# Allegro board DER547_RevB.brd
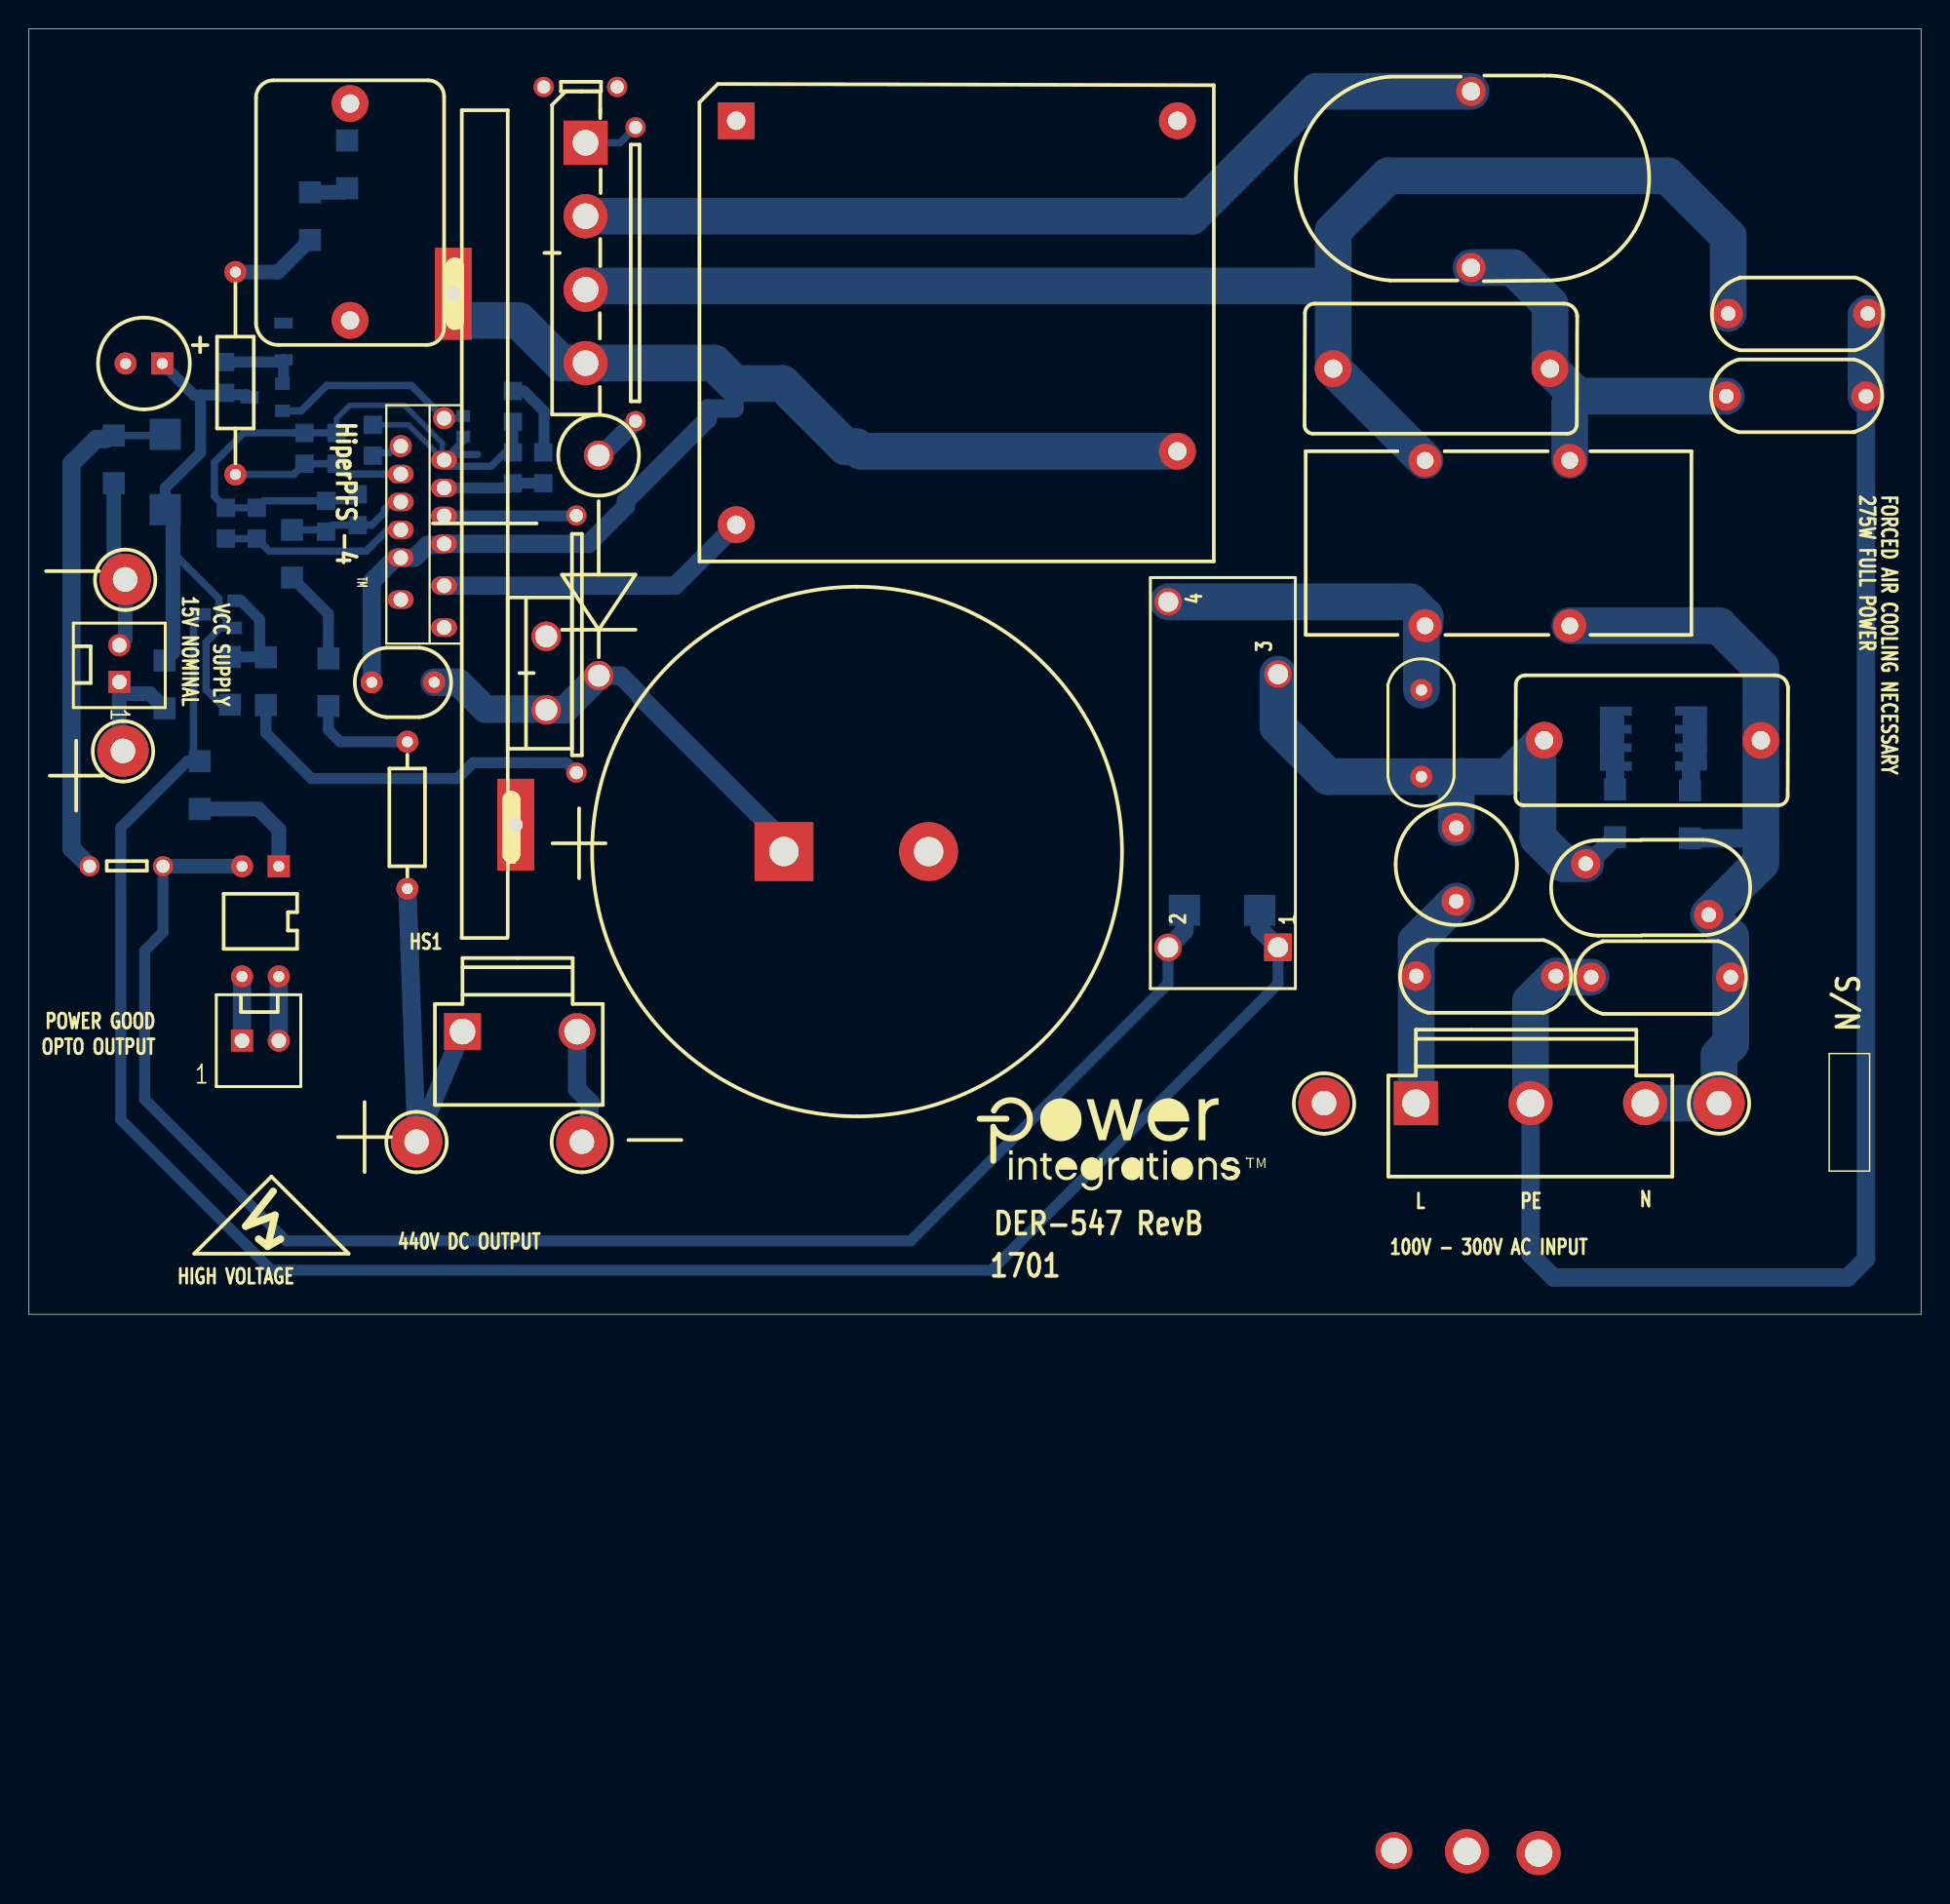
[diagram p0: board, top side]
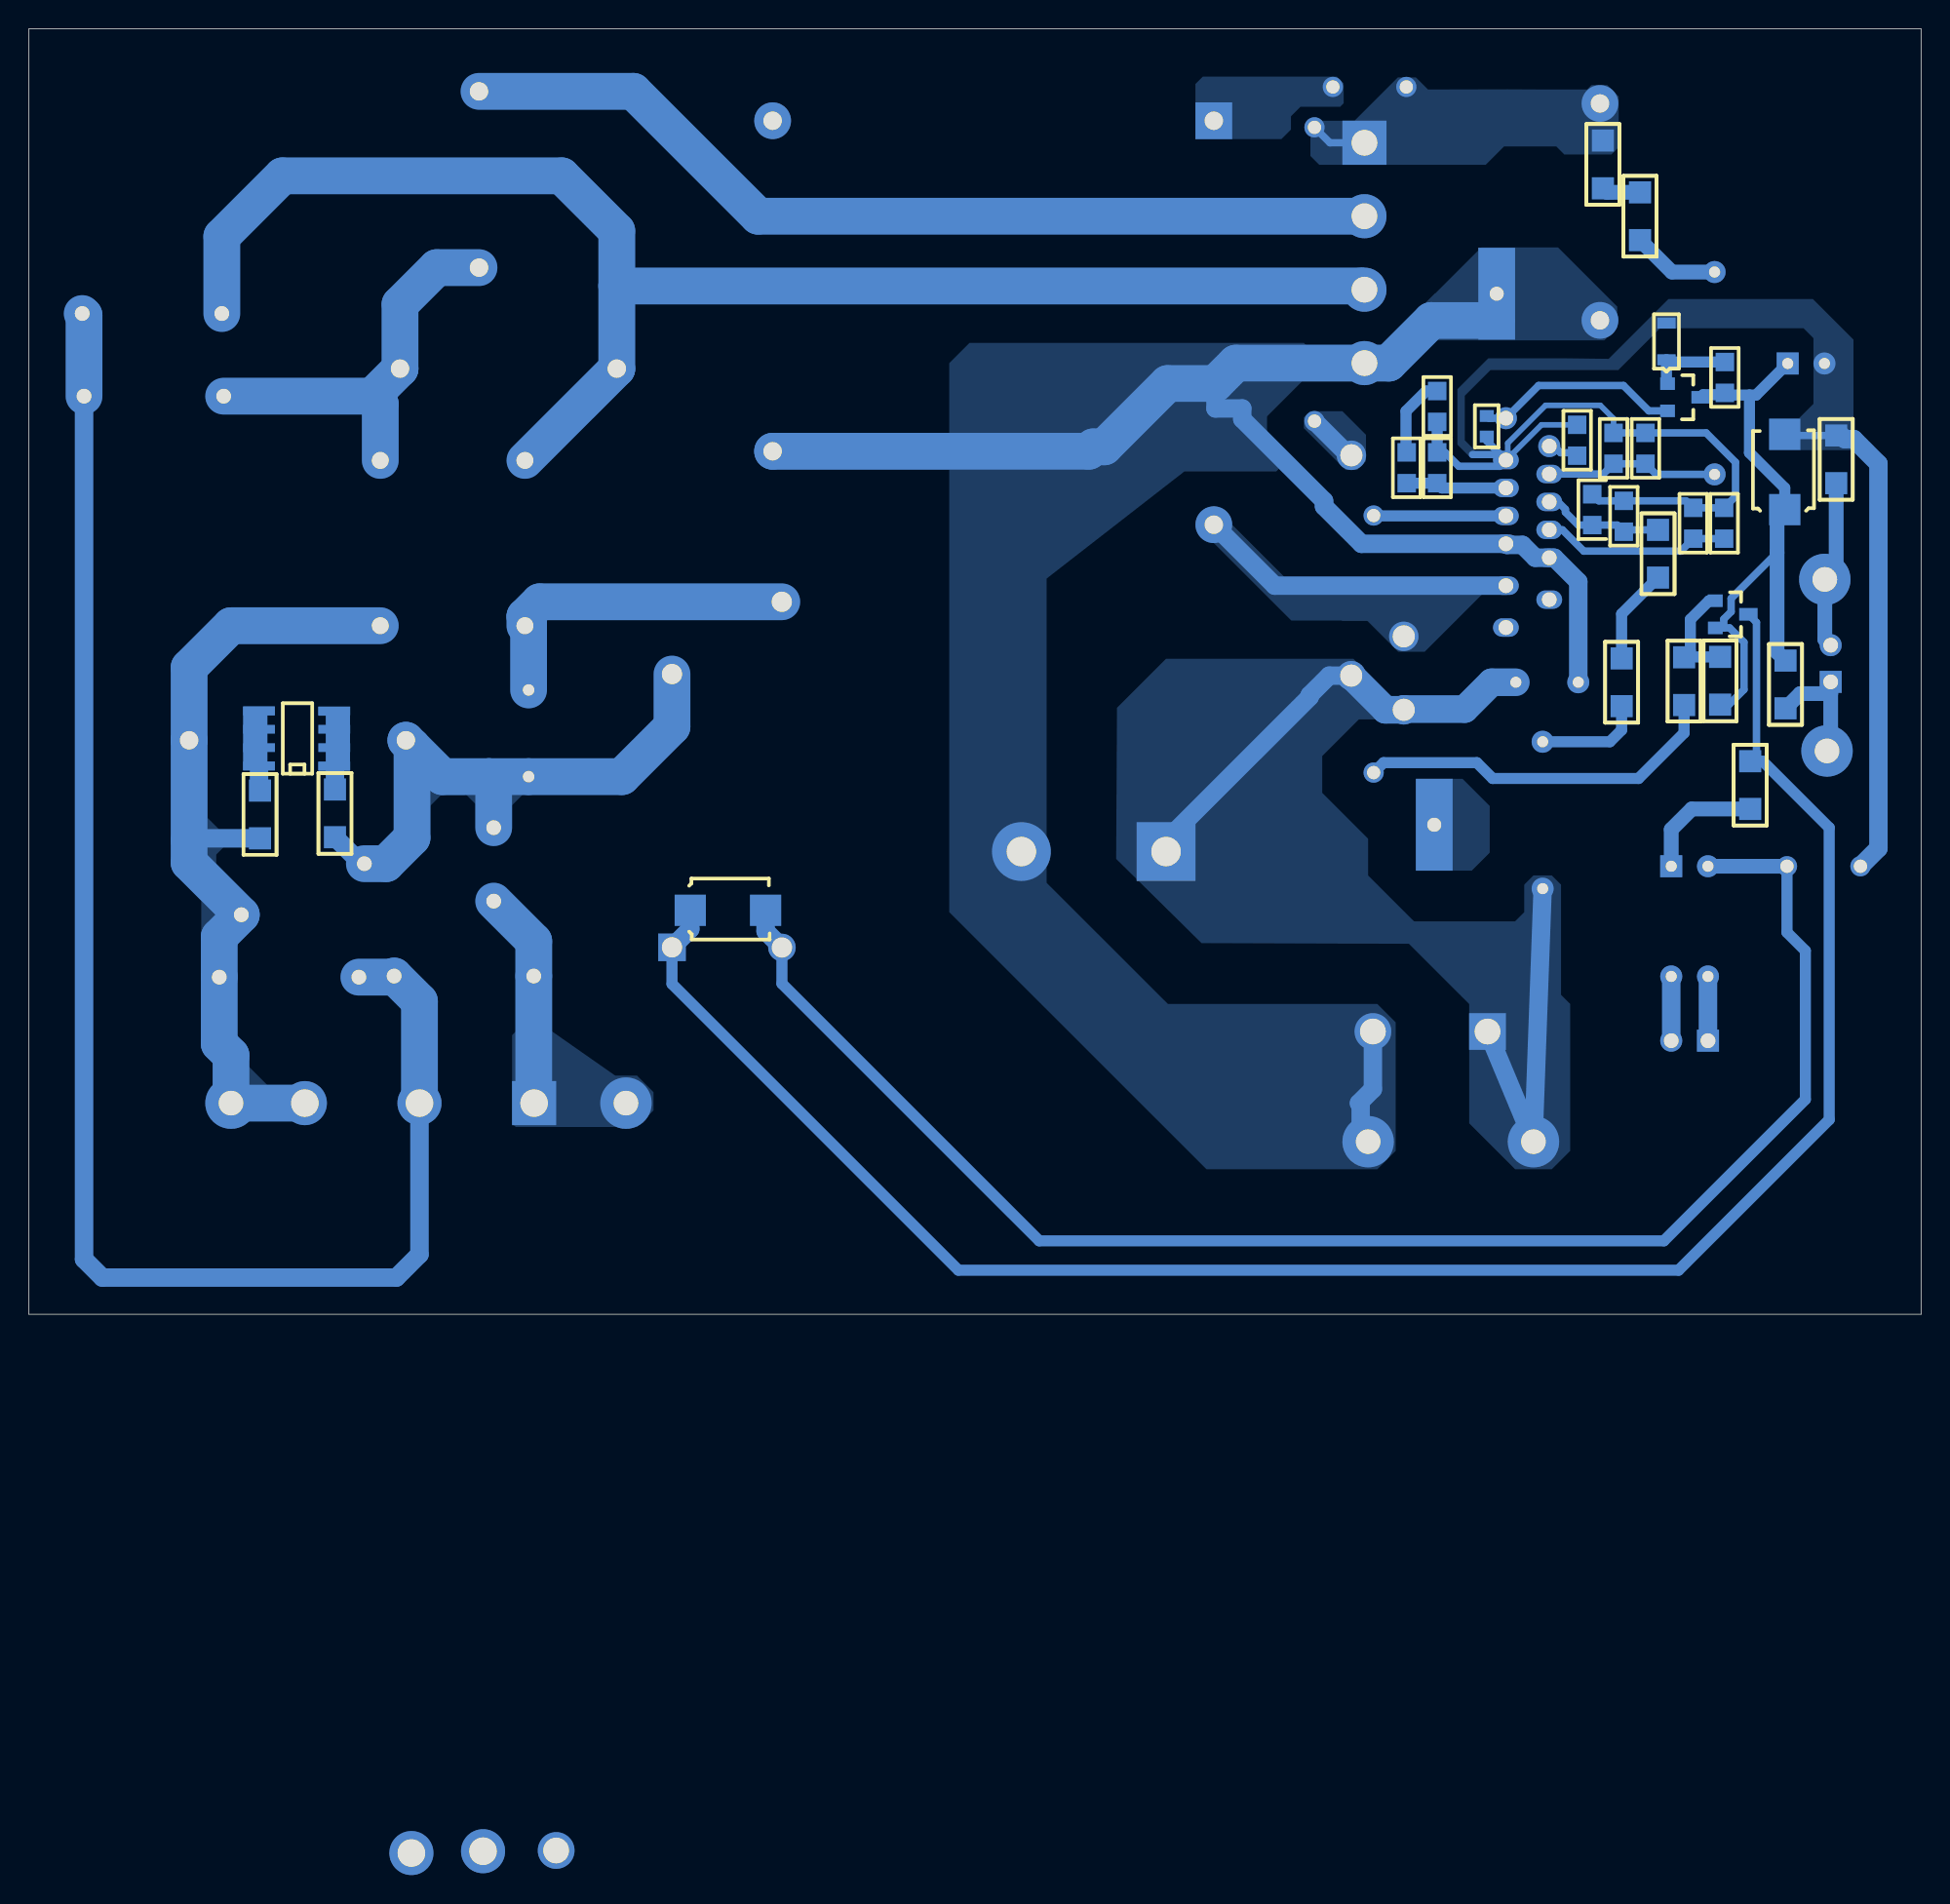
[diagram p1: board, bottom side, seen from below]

Outline 130.81 x 88.9 mm; copper layers: TOP, BOTTOM. Coordinates in mm from the lower left corner of the outline.
Outline path: 0,88.9 130.81,88.9 130.81,0 0,0 0,88.9

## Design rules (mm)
constraint set DEFAULT: min track width 0.508

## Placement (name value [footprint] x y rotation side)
BR1  GBU8K-BP  [PIDAXBRIDGEGBU8]  38.48 81.03 270 top
C1  680 pF  [PINPYCAPRAD470X210LS380040]  95.91 23.39 0 top
C2  680 pF  [PINPYCAPRAD470X210LS380040]  108 23.32 0 top
C3  0.33 uF  [PI_NP_CAPRAD709X354LS590D050]  104.75 39.7 0 top
C4  0.33 uF  [PI_NP_CAPRAD709X354LS590D050]  90.17 65.41 0 top
C5  680 pF  [PINPYCAPRAD470X210LS380040]  117.47 69.22 0 top
C6  680 pF  [PINPYCAPRAD470X210LS380040]  127 63.5 180 top
C7  0.33 uF  [PI_NP_CAPRAD717X472LS590D050]  22.2 83.74 270 top
C8  47 uF  [PIPOLCAPCYLD250LS100030]  9.22 65.76 180 top
C9  1 uF  [PISMC0603]  30.02 62.13 270 bottom
C10  1 uF  [PISMC0805]  23.77 59.39 90 bottom
C11  470 pF  [PISMC0805]  21.26 58.83 90 bottom
C12  100 nF  [PISMC0805]  33.45 57.48 90 bottom
C13  1 uF  [PISMC0805]  33.45 63.86 270 bottom
C14  1 nF  [PISMC0805]  15.75 53.64 90 bottom
C15  10 nF  [PI_NP_CAP250X200LS170D030]  28.02 43.71 180 top
C16  470 pF  [PISMC0805]  22.73 54.58 90 bottom
C18  180 uF  [PIPOLCAPCLYD1377LS394060]  52.2 32 0 top
D1  S1AB-13-F  [PISMSMB]  85.09 27.94 180 bottom
D2  1N5407-E3/54  [PIDV600X200X060DO14]  39.4 44.17 90 top
D3  S1AB-13-F  [PISMSMB]  9.42 55.65 90 bottom
D4  LXA06T600  [PIDVT0220ACREVA]  35.76 46.89 270 top
F1  5 A  [PI_TR5_SUBMIN_FUSE]  98.68 28.57 90 top
HS1  HEATSINK,  FAB, WITH BRKT, DER547, PI CUST  [PI_HS_DER394_EESIP]  33.1 26.11 90 top
J1  CON5  [PI_HDR_5PIN]  95.89 14.61 270 top
J2  CON2  [PI_MOLEX_2POL]  14.73 18.92 0 top
J3  CON3  [PI_HDR_3PIN_LOCK]  29.97 19.56 270 top
J4  CON2  [PI_MOLEX_2POL]  6.25 43.74 90 top
JP1  J  [PI_JUMPER200]  35.59 84.89 0 top
JP3  J  [PI_JUMPER200]  4.19 30.99 0 top
JP4  J  [PI_JUMPER800]  41.94 82.09 270 top
JP5  J  [PI_JUMPER700]  37.85 37.47 90 top
L1  400 uH  [PI_BOBBIN_BPQ32_20_32-00298-00]  48.9 82.55 0 top
L2  9 mH  [PI_IND_4P_500X1050LS450D46_R1]  96.52 47.62 90 top
L3  330 uH  [PI_TOROID_2P_550X950_LS480_D050]  99.69 72.39 90 top
NOREF  -  []  -213.36 -114.68 0 top
NOREF#2  -  []  0 0 90 top
NOREF#3  -  []  -135.54 84.33 0 top
NOREF#4  -  []  0 88.9 0 top
NOREF#5  -  []  65.53 14.99 0 top
Q1  -  [PISMSOT23132]  14.22 47.47 270 bottom
Q2  MMBT4401LT1G  [PISMSOT23132]  17.53 62.48 270 bottom
R1  510 k  [PISMR1206]  109.65 32.99 90 bottom
R2  510 k  [PISMR1206]  114.83 36.22 270 bottom
R3  10.0 k  [PISMR1206]  13.89 42.16 90 bottom
R4  16.2 k  [PISMR1206]  16.38 45.44 270 bottom
R5  3.01 k  [PISMR1206]  11.81 38.25 270 bottom
R6  1  [PISMR1206]  9.37 41.91 90 bottom
R7  1  [PISMR1206]  5.87 57.48 90 bottom
R8  2.21 k  [PISMR0805]  13.56 63.73 90 bottom
R10  6.2 M  [PISMR1206]  22 81.18 270 bottom
R11  6.2 M  [PISMR1206]  19.43 77.6 270 bottom
R12  3.74 M  [PI14WVRESD100LS100D030]  14.27 70.79 270 top
R13  143 k  [PISMR0805]  19.05 58.83 90 bottom
R14  30.1 k  [PISMR0805]  35.56 57.48 90 bottom
R15  332 k  [PISMR0805]  13.61 53.64 90 bottom
R16  3.74 M  [PI14WVRESD100LS100D030#2]  26.16 29.44 90 top
R17  6.2 M  [PISMR1206]  20.7 42.06 90 bottom
R18  6.2 M  [PISMR1206]  18.19 54.25 270 bottom
R19  143 k  [PISMR0805]  20.55 56.26 270 bottom
RL1  SPST NO  [PI_RLY-OMRON-G6RL-1A]  86.36 25.4 90 top
RT1  2.5  [PI_RAD180X395LS235D031]  96.27 37.19 90 top
RV1  420 Vac  [PIDISC500X225LS335X140040]  107.62 31.17 0 top
TP1  CON1  [PITPKEYSTONE125X125]  89.53 14.61 0 top
TP2  CON1  [PITPKEYSTONE125X125]  116.84 14.61 0 top
TP4  CON1  [PITPKEYSTONE125X125]  6.5 38.96 0 top
TP5  CON1  [PITPKEYSTONE125X125]  6.65 50.83 0 top
TP6  CON1  [PITPKEYSTONE125X125]  26.8 11.94 0 top
TP7  CON1  [PITPKEYSTONE125X125]  38.23 11.94 0 top
U1  PFS7627H  [PI_IC_ESIP16-13_SOCKET_HPII]  28.7 61.98 270 top
U2  CAP200DG  [PI_IC_SMD_SO8_CAPZERO]  109.7 37.92 90 bottom
U3  LTV817A  [PI_DIP4]  17.27 30.99 180 top
VR1  BZX384-B13,115  [PISMSOD323]  17.6 66.01 90 bottom

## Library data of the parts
BR1 = DISCRETE BRIDGE_+~~-
C1 C2 C5 C6 = CAP NP: tolerance: 20
C3 C4 C7 C9-C16 = CAP NP
C8 = CAP POL: alternate symbols: (pipolcapcyld250ls100030h); tolerance: 20
C18 = CAP POL
D1 D3 D4 = DIODE
D2 = DIODE: alternate symbols: (pidax800x225060do15do201ad,pidv300x200x060do14wbead,pidv600x200x060do14)
F1 = FUSE
HS1 = HS-PI_CUSTOM2
J1 = CON5
J2 J4 = CON2
J3 = CON3
JP1 JP3-JP5 = JUMPER_1
L1 = INDUCTOR_DER394_32-00298-00
L2 = INDUCTOR_4P_revB
L3 = INDUCTOR
Q1 = PNP_BEC_PISMSOT23132_MMBT4403
Q2 = NPN_BEC
R1-R8 R10 R11 R13-R15 R17-R19 = R
R12 R16 = R: alternate symbols: (pi14wvresd100ls200d030,pi14wresd100ls400d030,pi14wresd100ls500d030)
RL1 = RELAY SPST_NO_OMRON-G6RL
RT1 = THERMISTOR
RV1 = VARISTOR
TP1 TP2 TP4-TP7 = TESTPOINT
U1 = HIPERPFS-4-eSIP-16G: alternate symbols: (pi_ic_esip16-13_socket_hpii,pi_ic_esip16-13_oval_hpii,pi_ic_eesip_socket)
U2 = CAPZero
U3 = OPTO_DIP
VR1 = DIODE_ZENER

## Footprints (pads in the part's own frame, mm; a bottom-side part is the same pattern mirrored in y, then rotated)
PI14WVRESD100LS100D030
  round 1.524 hole 0.762: 1(-1.295,0) 2(12.7,0)
PI14WVRESD100LS100D030#2
  round 1.524 hole 0.762: 1(0,0) 2(10.16,0)
PI_BOBBIN_BPQ32_20_32-00298-00
  round 2.54 hole 1.27: (30.5,0) 6(0,-27.94) 8(30.5,-22.86)
  rect 2.54x2.54 hole 1.27: 1(0,0)
PI_DIP4
  rect 1.524x1.524 hole 0.762: 1(0,0)
  round 1.524 hole 0.762: 2(2.54,0) 3(2.54,7.62) 4(0,7.62)
PI_HDR_3PIN_LOCK
  rect 2.54x2.54 hole 1.778: 1(0,0)
  round 2.54 hole 1.778: 2(56.642,64.389) 3(0,7.925)
PI_HDR_5PIN
  rect 3.048x3.048 hole 1.905: 1(0,0)
  round 3.048 hole 1.905: 2(51.74,3.531) 3(0,7.925) 4(51.867,8.484) 5(0,15.85)
PI_HS_DER394_EESIP
  rect 6.35x2.54 hole 0.965: 1(7.747,-0.559) 2(44.475,3.759)
PI_IC_ESIP16-13_SOCKET_HPII
  round 1.524 hole 1.016: 1(0,0) 3(1.93,-2.997)
  oval 1.27x1.778 hole 1.016: 4(2.896,0) 5(3.861,-2.997) 6(4.826,0) 7(5.791,-2.997) 8(6.756,0) 9(7.722,-2.997) 10(8.687,0) 11(9.652,-2.997) 13(11.582,0) 14(12.548,-2.997) 16(14.478,0)
PI_IC_SMD_SO8_CAPZERO
  rect 0.599x2.2 smd: 1(0,0) 2(1.27,0) 3(2.54,0) 4(3.81,0) 5(3.81,5.199) 6(2.54,5.199) 7(1.27,5.199) 8(0,5.199)
PI_IND_4P_500X1050LS450D46_R1
  round 2.286 hole 1.168: 1(0,-10) 2(11.43,-10) 3(0,0) 4(11.43,0)
PI_JUMPER200
  round 1.397 hole 0.914: 1(0,0) 2(5.08,0)
PI_JUMPER700
  round 1.397 hole 0.914: 1(0,0) 2(17.78,0)
PI_JUMPER800
  round 1.397 hole 0.914: 1(0,0) 2(20.32,0)
PI_MOLEX_2POL
  rect 1.524x1.524 hole 1.016: 1(0,0)
  round 1.524 hole 1.016: 2(2.54,0)
PI_NP_CAP250X200LS170D030
  round 1.524 hole 0.762: 1(0,0) 2(4.318,0)
PI_NP_CAPRAD709X354LS590D050
  round 2.54 hole 1.27: 1(0,0) 2(14.986,0)
PI_NP_CAPRAD717X472LS590D050
  round 2.54 hole 1.27: 1(0,0) 2(15,0)
PI_RAD180X395LS235D031
  round 1.524 hole 0.787: 1(0,0) 2(5.994,0)
PI_RLY-OMRON-G6RL-1A
  rect 1.905x1.905 hole 1.397: 1(-0.02,0.008)
  round 1.905 hole 1.397: 2(-0.031,7.607) 3(18.88,0.008) 4(23.878,7.597)
PI_TOROID_2P_550X950_LS480_D050
  round 2.032 hole 1.27: 1(0,0) 2(12.192,0)
PI_TR5_SUBMIN_FUSE
  round 2.032 hole 1.016: 1(0,0) 2(5.08,0)
PIDAXBRIDGEGBU8
  rect 3.048x3.048 hole 1.778: 1(0,0)
  round 3.048 hole 1.778: 2(5.08,0) 3(10.16,0) 4(15.24,0)
PIDISC500X225LS335X140040
  round 2.032 hole 1.016: 1(0,0) 2(8.509,-3.531)
PIDV600X200X060DO14
  round 2.032 hole 1.524: 1(0,0) 2(15.24,0)
PIDVT0220ACREVA
  round 2.032 hole 1.524: 1(5.08,0) 2(0,0)
PINPYCAPRAD470X210LS380040
  round 2.032 hole 1.016: 1(0,0) 2(9.652,0)
PIPOLCAPCLYD1377LS394060
  rect 4.064x4.064 hole 2.032: 1(0,0)
  round 4.064 hole 2.032: 2(10,0)
PIPOLCAPCYLD250LS100030
  rect 1.524x1.524 hole 0.762: 1(0,0)
  round 1.524 hole 0.762: 2(2.54,0)
PISMC0603
  rect 0.813x0.965 smd: 1(0,0) 2(1.422,0)
PISMC0805
  rect 1.27x1.27 smd: 1(0,0) 2(2.134,0)
PISMR0805
  rect 1.27x1.27 smd: 1(0,0) 2(2.134,0)
PISMR1206
  rect 1.524x1.524 smd: 1(0,0) 2(3.302,0)
PISMSMB
  rect 2.159x2.159 smd: 1(0,0) 2(5.207,0)
PISMSOD323
  rect 0.762x1.27 smd: 1(0,0) 2(2.54,0)
PISMSOT23132
  rect 0.864x1.016 smd: 1(-1.88,0) 2(0,0)
  rect 0.864x1.27 smd: 3(-0.94,2.286)
PITPKEYSTONE125X125
  round 3.556 hole 1.702: 1(0,0)

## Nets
GND_EARTH: C1.2 C2.1 C5.2 C6.1 J1.3
K: U1.16
RTN: BR1.4 C7.2 C15.2 C18.2 HS1.2 J3.3 L1.8 TP7.1 U1.10 U1.11
VRECT: BR1.1 C7.1 JP1.1 JP4.1 R10.1
N07467: C15.1 C18.1 D2.1 D4.1 J3.1 R16.1 TP6.1
N25080: C8.1 D3.1 Q1.2(EMITTER) Q2.3 R3.1 R6.2 R8.1
N182027: C8.2 C9.2 C10.2 C11.2 C12.2 C13.2 C14.2 C16.2 D3.2 JP3.1 R7.2 R13.2 R15.2 R19.1 U1.4 VR1.2
N186578: J4.1 R6.1 TP4.1
N737447: J4.2 R7.1 TP5.1
N1260162: C9.1 Q2.2(EMITTER) U1.1(VCC)
N1260176: JP5.2 U1.8
N1270725: C2.2 C3.2 J1.5 L2.1 R2.2 RV1.2 TP2.1
N1270759: BR1.3(AC2) C4.1 C5.1 L2.4
N1270767: C4.2 C6.2 L2.2 L3.1
N1270943: BR1.2 L3.2
N1271019: R1.2 U2.1 U2.2 U2.3 U2.4
N1271113: C3.1 F1.2 R1.1 RL1.3 RT1.1 RV1.1
N1271129: C1.1 F1.1 J1.1 TP1.1
N1844572: D1.2 JP3.2 RL1.2 U3.2
N1847765: Q1.1 R3.2 R4.1
N1847834: JP5.1 R4.2
N1847930: D1.1 Q1.3 R5.1 RL1.1
N1948021: J2.1 U3.3(E)
N1951038: J2.2 U3.4
N2021552: R2.1 U2.5 U2.6 U2.7 U2.8(NC8)
N2052551: L2.3 RL1.4(NO) RT1.2
N2109009: R16.2 R17.1
N2109013: R17.2 R18.2
N2109017: C16.1 R18.1 R19.2 U1.7
N2110256: C14.1 R15.1 U1.9
N2110453: C13.1 R14.2
N2110457: C12.1 R14.1 U1.6
N2110683: C11.1 R12.2 R13.1 U1.5
N2110757: C10.1 U1.3
N2114150: R10.2 R11.1
N2114158: R11.2 R12.1
N2163226: JP1.2 L1.1
N2199044: Q2.1 R8.2 VR1.1
N2237206: D4.2 L1.6 U1.13
N2267541: D2.2 JP4.2
N2322962: HS1.1
N19475010: R5.2 U3.1

Pads without a net: J1 2 4; J3 2; U1 14

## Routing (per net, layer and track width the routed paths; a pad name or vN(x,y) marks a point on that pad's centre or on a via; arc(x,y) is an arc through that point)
GND_EARTH: length 112.3
  BOTTOM w1.27: C6.1 127,3.81 125.73,2.54 105.41,2.54 103.81,4.14 J1.3
  BOTTOM w2.54: C2.1 105.64,23.32 C1.2 103.81,21.64 J1.3 ; C5.2 127,69.09 C6.1
RTN: length 103.4
  BOTTOM w1.27: TP7.1 38.86,12.57 38.74,12.69 38.74,14.49 38.86,14.61 37.9,15.57 J3.3 ; 29.38,68.73 29.62,70.61 ; C15.2 23.7,50.67 25.35,52.32 U1.11 26.67,52.32 27.56,53.21 28.63,53.21 U1.10 38.68,53.29 41.27,55.88 41.27,56.26 46.93,61.91 46.93,62.65 48.78,62.65 48.78,64.38
  BOTTOM w2.54: 29.38,68.73 33.86,68.73 36.8,65.79 BR1.4 47.37,65.79 48.78,64.38 52.08,64.38 56.46,59.99 57.23,59.99 57.53,59.69 L1.8
VRECT: length 3.9
  BOTTOM w0.508: BR1.1 40.87,81.03 JP4.1
N07467: length 57.3
  BOTTOM w1.27: C18.1 52.2,32.77 42.27,42.7 42.27,42.82 40.92,44.17 D2.1 ; J3.1 TP6.1 R16.1
  BOTTOM w1.905: C15.1 29.69,43.71 31.55,41.86 35.71,41.86 D4.1 37.03,41.81 D2.1
N25080: length 41.4
  BOTTOM w0.508: Q1.2 13.64,47.47 ; 13.64,47.47 13.64,48.08 13.13,48.59 13.13,49.5 9.96,52.68 ; 13.64,47.47 13.23,47.47 12.24,46.48 12.24,43.21 13.28,42.16 R3.1
  BOTTOM w0.762: 11.86,63.58 13.41,63.58 R8.1 13.69,63.6 15.06,63.6 Q2.3 ; 11.86,63.58 11.4,63.58 C8.1 ; 11.86,63.58 11.86,59.59 9.42,57.15 D3.1
  BOTTOM w1.016: D3.1 9.96,55.12 9.96,45.8 R6.2
N182027: length 86.4
  BOTTOM w0.381: C11.2 21.26,61.95 22.17,62.87 25.96,62.87 28.57,60.25 28.57,59.21 U1.4 28.68,59.08 26.24,61.52 C10.2
  BOTTOM w0.508: D3.2 9.35,60.78 R7.2 ; 29.08,59.46 30.02,60.4 C9.2 ; 29.08,59.46 31.01,59.46 ; 29.08,59.46 U1.4 29.13,58.65 31.95,58.65 32.92,59.61 C12.2 ; C16.2 22.28,56.26 R19.1 16.26,56.26 15.77,55.78 C14.2 R15.2 12.83,56.57 12.83,58.93 14.86,60.96 R13.2 C11.2
  BOTTOM w0.762: C13.2 C12.2
  BOTTOM w1.27: R7.2 5.54,60.78 5.28,60.53 4.65,60.53 2.95,58.83 2.95,32.23 JP3.1
N186578: length 8.4
  BOTTOM w1.016: 6.25,42.93 6.25,39.22 TP4.1 ; 6.25,42.93 8.36,42.93 R6.1 ; 6.25,42.93 J4.1
N737447: length 11.7
  BOTTOM w1.016: J4.2 6.65,46.69 TP5.1 5.87,51.61 R7.1
N1260162: length 14.2
  BOTTOM w0.508: Q2.2 18.82,62.48 20.57,64.24 26.44,64.24 U1.1 29.87,61.98 C9.1
N1260176: length 9.2
  BOTTOM w0.762: 37.85,55.24 37.82,55.22 U1.8
N1270725: length 57.1
  BOTTOM w1.27: R2.2 119.61,32.92 119.74,32.79
  BOTTOM w2.54: L2.1 116.84,47.62 119.74,44.73 C3.2 119.74,31.24 RV1.2 117.65,26.11 C2.2 117.65,18.72 116.84,17.91 TP2.1 111.73,14.61
N1270759: length 106.3
  BOTTOM w2.54: 90.17,71.12 90.17,74.93 93.98,78.74 113.28,78.74 117.47,74.55 C5.1 ; 90.17,71.12 38.73,71.12 BR1.3 ; 90.17,71.12 C4.1 L2.4
N1270767: length 28.6
  BOTTOM w2.54: 107.06,63.5 106.52,62.96 L2.2 ; 107.06,63.5 C4.2 105.16,69.85 102.62,72.39 L3.1 ; 107.06,63.5 C6.2
N1270943: length 64.8
  BOTTOM w2.54: BR1.2 80.39,75.95 89.03,84.58 L3.2
N1271019: length 1.6
  BOTTOM w1.27: R1.2 109.65,37.87 U2.1
N1271113: length 41.3
  BOTTOM w1.27: R1.1 107.82,31.17 RV1.1
  BOTTOM w2.54: C3.1 104.33,39.28 ; 104.33,39.28 102.23,37.19 99.01,37.19 ; 104.33,39.28 104.33,32.96 106.12,31.17 RV1.1 ; 99.01,37.19 RT1.1 89.81,37.19 86.35,40.65 RL1.3 ; 99.01,37.19 98.68,36.86 F1.2
N1271129: length 15.1
  BOTTOM w2.54: F1.1 95.91,25.81 C1.1 95.91,14.63 J1.1
N1844572: length 109.8
  BOTTOM w0.762: JP3.2 9.27,26.42 8,25.15 8,14.86 17.78,5.08 60.96,5.08 78.75,22.87 RL1.2
  BOTTOM w1.016: U3.2 JP3.2
  BOTTOM w1.27: RL1.2 79.88,26.5 D1.2
N1847765: length 7.5
  BOTTOM w0.762: 16.36,45.47 R4.1 ; 16.36,45.47 15.95,45.87 15.95,48.06 14.66,49.35 Q1.1 ; 16.36,45.47 R3.2
N1847834: length 25.4
  BOTTOM w0.762: JP5.1 37.16,38.15 30.71,38.15 29.62,37.06 19.53,37.06 16.38,40.21 R4.2
N1847930: length 136.3
  BOTTOM w0.508: Q1.3 11.38,47.85 11.38,38.68 R5.1
  BOTTOM w0.762: R5.1 10.95,38.25 6.35,33.66 6.35,13.46 16.76,3.05 66.55,3.05 86.35,22.85 RL1.1
  BOTTOM w1.27: RL1.1 85.09,26.64 D1.1
N1948021: length 4.4
  BOTTOM w1.27: U3.3 J2.1
N1951038: length 4.4
  BOTTOM w1.27: U3.4 J2.2
N2021552: length 1.7
  BOTTOM w1.27: U2.8 114.9,36.29 R2.1
N2052551: length 24
  BOTTOM w2.54: L2.3 96.52,48.26 ; 96.52,48.26 95.5,49.28 RL1.4 ; 96.52,48.26 96.27,48.01 RT1.2
N2109009: length 7.4
  BOTTOM w0.762: R16.2 21.51,39.6 20.7,40.41 R17.1
N2109013: length 6.6
  BOTTOM w0.762: R17.2 20.7,48.44 R18.2
N2109017: length 8.5
  BOTTOM w0.508: R18.1 20.42,54.25 R19.2 21.01,54.58 C16.1 23.7,54.58 24.59,55.47 24.59,55.68 25.1,56.18 U1.7
N2110256: length 13.1
  BOTTOM w0.508: U1.9 24.79,54.25 23.32,52.78 16.61,52.78 C14.1 R15.1
N2110453: length 5.6
  BOTTOM w0.762: R14.2 35.61,59.66 35.61,62.46 34.21,63.86 C13.1
N2110457: length 7
  BOTTOM w0.762: U1.6 33.12,57.15 C12.1 R14.1
N2110683: length 12
  BOTTOM w0.508: U1.5 21.97,58.12 C11.1 R13.1 18.31,58.09 R12.2
N2110757: length 2.2
  BOTTOM w0.508: U1.3 25.37,60.05 24.92,59.59 23.98,59.59 C10.1
N2114150: length 2.7
  BOTTOM w1.016: R11.1 21.72,77.6 R10.2
N2114158: length 6.1
  BOTTOM w1.016: R12.1 17.22,72.09 19.43,74.3
N2199044: length 5.8
  BOTTOM w0.762: Q2.1 17.6,64.44 VR1.1 17.45,65.86 R8.2
N2237206: length 21.9
  BOTTOM w1.27: L1.6 44.68,50.39 U1.13
N2267541: length 3.5
  BOTTOM w1.27: JP4.2 39.57,59.41 D2.2
N19475010: length 8.6
  BOTTOM w1.016: U3.1 17.27,33.53 15.85,34.95 R5.2

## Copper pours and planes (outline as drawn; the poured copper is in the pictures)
RTN on BOTTOM: 37.59,10.03 36.32,11.3 36.32,20.19 37.59,21.46 52.07,21.46 60.45,29.84 60.45,50.88 50.93,58.29 44.58,58.29 43.94,58.93 43.94,59.56 45.21,60.83 45.21,62.1 42.04,65.28 42.04,66.55 42.67,67.18 65.79,67.18 67.18,65.79 67.18,27.81 49.4,10.03
RTN on BOTTOM: 30.4,73.79 33.58,70.61 33.6,70.61 35.05,69.16 35.08,69.16 35.08,67.36 21.89,67.36 21.01,68.25 21.01,69.7 25.1,73.79
VRECT on BOTTOM: 30.1,79.5 28.83,80.77 25.22,80.77 24.66,80.21 21.41,80.21 20.9,80.72 20.9,84.23 21.69,85.01 22.79,85.01 23.08,84.71 25.96,84.71 28.56,84.72 34.09,84.71 34.92,85.55 36.17,85.55 39.17,82.55 41.45,82.55 42.21,81.79 42.21,80.11 41.61,79.5
N07467 on BOTTOM: 36.7,42.8 36.7,41.15 38.86,41.15 41.4,38.61 41.4,36.07 38.23,32.89 38.23,30.35 35.05,27.18 28.07,27.18 27.43,27.81 27.43,29.72 26.8,30.35 25.53,30.35 24.89,29.72 24.89,22.1 24.26,21.46 24.26,11.3 25.53,10.03 28.07,10.03 31.24,13.21 31.24,21.46 35.4,25.63 49.74,25.67 55.65,31.5 55.59,41.95 52.2,45.34 39.24,45.34
N182027 on BOTTOM: 30.73,59.28 30.71,59.31 30.71,59.61 31.55,60.45 31.55,63.53 29.77,65.3 20.93,65.3 18.03,68.2 12.47,68.2 12.46,68.19 12.46,68.2 8.13,68.2 7.44,67.51 7.44,62.97 8.43,61.98 10.49,61.98 10.49,59.77 4.8,59.77 4.67,59.89 4.67,67.41 7.48,70.22 17.46,70.22 21.6,66.08 24.51,66.12 29.92,66.12 32.05,63.98 32.05,60.15 31.19,59.28
N1270725 on BOTTOM: 118.67,34.54 117.2,33.07 117.2,32.46 117.86,31.8 117.86,30.61 117.73,30.48 119.63,30.48 120.17,31.01 120.17,34.11 119.74,34.54
N1270725 on BOTTOM: 118.9,26.19 118.9,29.03 117.53,29.03 117.53,26.19
N1270725 on BOTTOM: 114.1,15.67 114.15,15.67 115.98,17.5 116.1,17.37 116.1,15.11 114.27,15.11 114.1,15.29
N1271019 on BOTTOM (solid shape): 110.79,41.4 110.29,41.4 110.29,38.2 110.79,38.2 110.79,37.59 108.61,37.59 108.61,42.01 110.79,42.01
N1271113 on BOTTOM: 96.55,36.07 97.79,34.82 99.47,34.82 100.62,35.98 100.71,35.89 102.34,35.89 103.56,34.67 103.94,35.05 103.94,36.7 103.84,36.8 96.9,36.8 96.55,36.45
N1271129 on BOTTOM: 90.28,16.51 94.81,19.68 97.03,19.68 97.41,19.3 97.41,13.21 97.16,12.95 88.77,12.95 87.63,14.1 87.63,15.37 88.77,16.51
N2021552 on BOTTOM (solid shape): 116,37.62 113.82,37.62 113.82,38.23 114.33,38.23 114.33,41.43 113.82,41.43 113.82,42.04 116,42.04
N2163226 on BOTTOM: 39.93,85.06 39.92,85.05 39.92,83.76 40.16,83.52 42.9,83.52 43.56,82.85 43.56,81.94 44.22,81.28 50.16,81.28 50.16,85.09 49.66,85.6 40.39,85.6 39.93,85.14
N2237206 on BOTTOM: 30.28,50.8 30.28,49.86 34.32,45.82 36.14,45.82 38.28,47.96 40.03,47.96 40.06,47.98 43.54,47.98 50.16,54.61 48.9,55.88 43.81,50.8
N2267541 on BOTTOM: 38.38,59 38.38,60.83 40.01,62.46 42.24,62.46 42.67,62.03 42.67,61.29 39.78,58.39 38.99,58.39
N2322962 on BOTTOM: 34.9,37.03 31.7,37.03 29.82,35.15 29.82,31.93 31.06,30.68 34.92,30.68 34.92,37.01

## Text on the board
Ref Des/Silkscreen Top: TM | OPTO OUTPUT | POWER GOOD | HIGH VOLTAGE | 440V DC OUTPUT | 100V - 300V AC INPUT | L | PE | N | 15V NOMINAL | VCC SUPPLY | 275W FULL POWER | FORCED AIR COOLING NECESSARY | HiperPFS -4 | 1701 | DER-547 RevB | S/N | - | +
User.6: SLOT1 | SLOT2
User.7: 13   MATERIALFR4 COPPER 2oz THICKNESS 0.062"
User.9: FIGURE | FINISHED_SIZE | 30.0 | 31.0 | 36.0 | 38.0 | 40.0 | 46.0 | 50.0 | 55.0 | 60.0 | 67.0 | 70.0 | 75.0 | 80.0 | DRILL CHART: TOP to BOTTOM | ALL UNITS ARE IN MILS | PLATED | QTY | 12 | 2 | 8 | 29 | 4 | 6 | 7 | 5
